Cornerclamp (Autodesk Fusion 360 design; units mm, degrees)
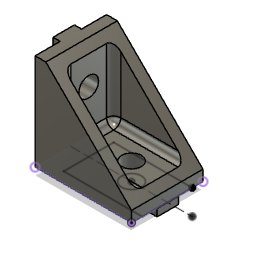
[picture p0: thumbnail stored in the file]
box_primitive "BoxPrimitive1" DistanceX 20 DistanceY 27 DistanceZ 27 OffsetDistanceX 0 OffsetDistanceY 0
sketch "Sketch5" plane through (0, 0, 35) normal (0, 0, 1) x axis (1, 0, 0)
  line L1 (-12, 0) -> (-12, 27)
  line L2 (15, 0) -> (-12, 0)
  line L3 (15, 27) -> (15, 0)
  line L4 (-12, 27) -> (15, 27)
  line L5 (15, 3) -> (-9, 27)
  line L6 (15, 27) -> (-12, 27)
  line L7 (15, 0) -> (15, 27)
  point P6 (-9, 27)
  point P7 (15, 3)
  coincident L4 P6
  coincident L3 P7
  dimension "d14" distance L1 P6 = 3
  dimension "d15" distance L2 P7 = 3
extrude "Extrude2" cut sketch "Sketch5" profile of L3 L4 L5 L6 L7 no distance stored
sketch "Sketch7" plane through (0, 0, 0) normal (0, -1, 0) x axis (1, 0, 0)
  line L1 (-12, 35) -> (15, 35)
  line L2 (-12, 15) -> (-12, 35)
  line L3 (15, 15) -> (-12, 15)
  line L4 (15, 35) -> (15, 15)
  line L5 (-12, 35) -> (15, 35)
  line L6 (15, 35) -> (15, 15)
  line L7 (15, 32) -> (-7, 32)
  line L8 (15, 18) -> (15, 32)
  line L9 (-7, 18) -> (15, 18)
  line L10 (-7, 32) -> (-7, 18)
  line L11 (22, 25) -> (-12, 25)
  circle C1 centre (5, 25) radius 2.75
  point P11 (15, 18)
  point P13 (-12, 25)
  point P15 (5, 25)
  horizontal L7
  vertical L8
  horizontal L9
  vertical L10
  coincident L6 P11
  midpoint L2 P13
  perpendicular L6 L11
  symmetric L7 L9 L11
  midpoint L11 P15
  dimension "d17" distance L7 L9 = 14
  dimension "d18" distance L2 L10 = 5
  dimension "d19" diameter C1 = 5.5
  dimension "d20" distance L10 P15 = 12
extrude "Extrude3" cut sketch "Sketch7" profile of C1 no distance stored
extrude "Extrude4" cut sketch "Sketch7" profile of L4 L6 L7 L8 L9 L10 C1 no distance stored from offset -5
sketch "Sketch8" plane through (-12, 0, 0) normal (-1, 0, 0) x axis (0, 0, 1)
  line L1 (15, 0) -> (15, 27)
  line L2 (35, 0) -> (15, 0)
  line L3 (35, 27) -> (35, 0)
  line L4 (15, 27) -> (35, 27)
  line L5 (32, 27) -> (18, 27)
  line L6 (32, 5) -> (32, 27)
  line L7 (18, 5) -> (32, 5)
  line L8 (18, 27) -> (18, 5)
  line L9 (25, 37) -> (25, 0)
  line L10 (32, 0) -> (18, 0)
  circle C1 centre (25, 17) radius 2.75
  point P6 (18, 27)
  point P10 (25, 0)
  point P14 (25, 17)
  horizontal L5
  vertical L6
  horizontal L7
  vertical L8
  coincident L4 P6
  midpoint L2 P10
  perpendicular L4 L9
  symmetric L6 L8 L9
  coincident L9 P14
  dimension "d24" distance L6 L8 = 14
  dimension "d25" distance L7 L10 = 5
  dimension "d26" diameter C1 = 5.5
  dimension "d27" distance L7 P14 = 12
extrude "Extrude5" cut sketch "Sketch8" profile of C1 no distance stored
sketch "Sketch9" plane through (0, 0, 0) normal (0, -1, 0) x axis (1, 0, 0)
  line L1 (22, 25) -> (-12, 25)
  line L2 (-12, 15) -> (-12, 35)
  line L3 (-2, 28) -> (-12, 28)
  line L4 (-2, 22) -> (-2, 28)
  line L5 (-12, 22) -> (-2, 22)
  line L6 (-12, 28) -> (-12, 22)
  line L7 (-12, 35) -> (15, 35)
  line L8 (1.5, 10) -> (1.5, 35)
  line L9 (9.5048, 28) -> (15.1398, 28)
  line L10 (9.5048, 22) -> (9.5048, 28)
  line L11 (15.1398, 22) -> (9.5048, 22)
  line L12 (15.1398, 28) -> (15.1398, 22)
  point P7 (-12, 28)
  point P13 (1.5, 35)
  point P8 (-2, 28)
  horizontal L3
  vertical L4
  horizontal L5
  vertical L6
  coincident L2 P7
  symmetric L1 L3 L5
  midpoint L7 P13
  perpendicular L7 L8
  horizontal L9
  vertical L10
  horizontal L11
  vertical L12
  collinear L3 L9
  collinear L5 L11
  dimension "d29" distance L3 L5 = 6
  dimension "d30" distance P7 P8 = 10
extrude "Extrude6" add sketch "Sketch9" profile of L1 L2 L3 L4 L5 L6 L9 L10 L11 L12 along normal blind 2
sketch "Sketch10" plane through (-12, 0, 0) normal (-1, 0, 0) x axis (0, 0, 1)
  line L1 (15, 0) -> (15, 27)
  line L2 (22, 0) -> (15, 0)
  line L3 (22, -2) -> (22, 0)
  line L4 (28, -2) -> (22, -2)
  line L5 (28, 0) -> (28, -2)
  line L6 (35, 0) -> (28, 0)
  line L7 (35, 27) -> (35, 0)
  line L8 (15, 27) -> (35, 27)
  line L9 (28, 10) -> (22, 10)
  line L10 (28, 21.5048) -> (22, 21.5048)
  line L11 (22, 0) -> (28, 0)
  line L12 (22, 10) -> (22, 0)
  line L13 (25, 34) -> (25, 0)
  line L14 (28, 0) -> (28, 10)
  line L15 (22, 21.5048) -> (22, 27.1398)
  line L16 (28, 27.1398) -> (28, 21.5048)
  line L17 (22, 27.1398) -> (28, 27.1398)
  circle C1 centre (25, 17) radius 2.75
  circle C2 centre (25, 17) radius 2.75
  dimension "d33" diameter C2 = 5.5
extrude "Extrude7" add sketch "Sketch10" profile of L8 L9 L10 L11 L12 L13 L14 L15 L16 along normal blind 2
fillet "Fillet1" radius 2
